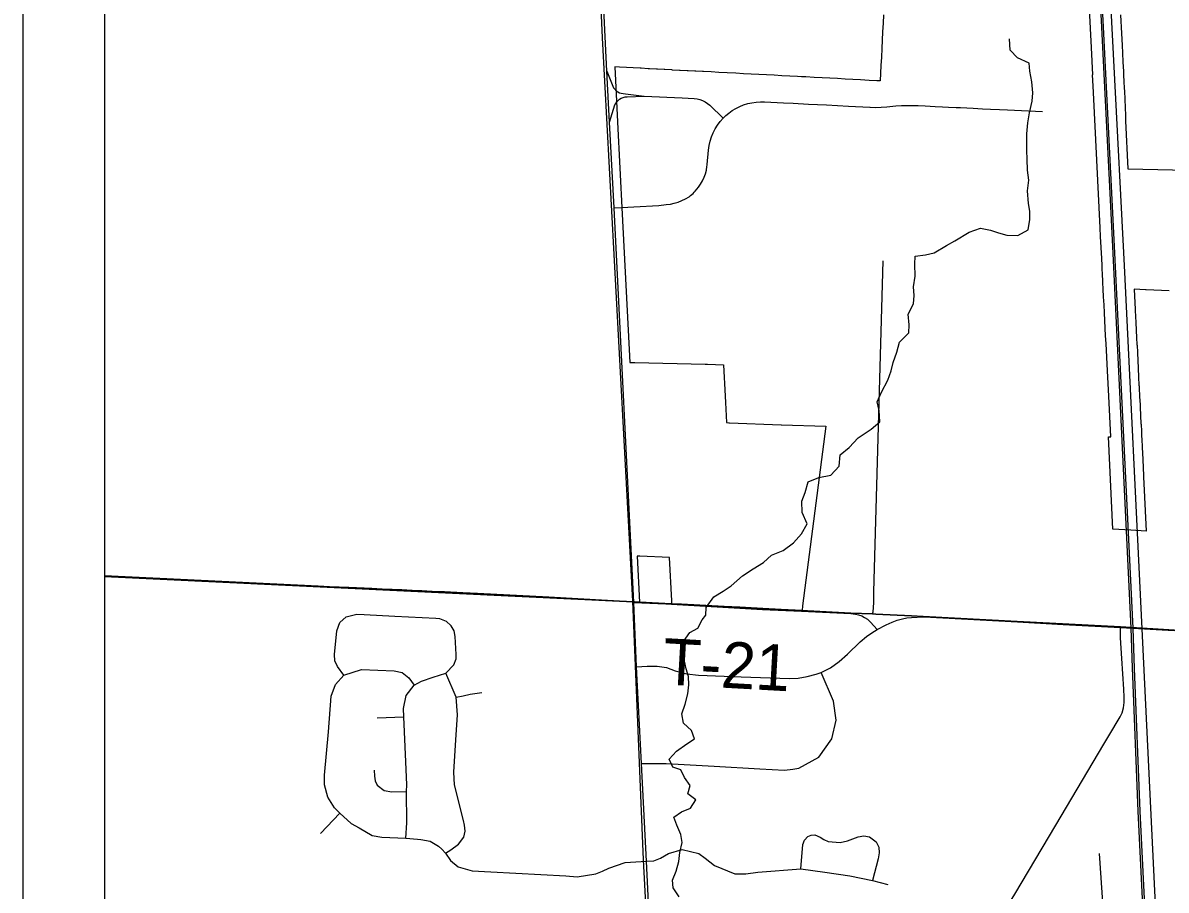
# Model space of a CAD drawing. Extents: x 0 to 34, y 0 to 22.
# Drawn here: x 22.011 to 23.415, y 8.323 to 9.388 of the extents above; entities that cross this region are included whole.
import ezdxf

# ---------------------------------------------------------------- set-up
doc = ezdxf.new("R2010")
doc.units = 0
for name, color, linetype in [('GM_X_City_Street', 7, 'Continuous'), ('GM_X_Corporation', 7, 'Continuous'), ('GM_X_County_Road', 7, 'Continuous'), ('GM_X_Minor_River', 7, 'Continuous'), ('GM_X_Rail_Line', 7, 'Continuous'), ('GM_X_Township_Road', 7, 'Continuous'), ('GM_X_Township_Road_Text', 7, 'Continuous'), ('GM_X_US_Route', 7, 'Continuous'), ('SH_Data', 7, 'Continuous')]:
    doc.layers.add(name, color=color, linetype=linetype)

msp = doc.modelspace()

# ---------------------------------------------------------------- linework, layer by layer
at = {"layer": 'GM_X_City_Street'}
for p, q in [((22.4461, 8.5349), (22.4786, 8.5364)), ((22.3764, 8.3929), (22.4001, 8.418))]:
    msp.add_line(p, q, dxfattribs=at)
for points in [[(22.728, 9.3292), (22.7362, 9.3086), (22.7376, 9.3067), (22.7393, 9.305), (22.7413, 9.3037), (22.7434, 9.3026), (22.7456, 9.3019), (22.748, 9.3015), (22.7509, 9.301), (22.7737, 9.2983)], [(22.7313, 9.2663), (22.7378, 9.2875), (22.7388, 9.2895), (22.7401, 9.2913), (22.7417, 9.2931), (22.7436, 9.2947), (22.7457, 9.2959), (22.748, 9.2968), (22.7504, 9.2974), (22.7529, 9.2976), (22.7737, 9.2983)], [(22.737, 9.1611), (22.7465, 9.1615), (22.761, 9.1625), (22.7916, 9.1642), (22.8009, 9.1652), (22.8059, 9.1658), (22.8107, 9.1669), (22.8155, 9.1683), (22.8201, 9.1701), (22.8246, 9.1723), (22.8289, 9.1748), (22.8308, 9.1765), (22.8322, 9.1776), (22.8339, 9.179), (22.8351, 9.1803), (22.8364, 9.1817), (22.8384, 9.1841), (22.8405, 9.1865), (22.8431, 9.1904), (22.8454, 9.1944), (22.8474, 9.1987), (22.849, 9.203), (22.8502, 9.2075), (22.8504, 9.2084), (22.8509, 9.2113), (22.8513, 9.2143), (22.8529, 9.2321), (22.8537, 9.2376), (22.8549, 9.2429), (22.8565, 9.2482), (22.8585, 9.2532), (22.861, 9.2581), (22.8639, 9.2628), (22.8671, 9.2673), (22.8707, 9.2714), (22.874, 9.2747), (22.8776, 9.2776), (22.8819, 9.2807), (22.8864, 9.2833), (22.8911, 9.2856), (22.8959, 9.2876), (22.9009, 9.2891), (22.906, 9.2903), (22.9112, 9.291), (22.9164, 9.2914), (22.9216, 9.2913), (22.9448, 9.2901), (22.9565, 9.2896), (22.9757, 9.2886), (22.9977, 9.2877), (23.0248, 9.2862), (23.0506, 9.2849), (23.0513, 9.2848), (23.058, 9.2845), (23.0648, 9.2846), (23.0715, 9.2852), (23.0827, 9.2863), (23.0897, 9.2868), (23.0968, 9.287), (23.1038, 9.2868), (23.11, 9.2867), (23.1189, 9.2865), (23.1309, 9.2858), (23.1399, 9.2853), (23.1475, 9.2849), (23.1569, 9.2844), (23.162, 9.2843), (23.1777, 9.2835), (23.1893, 9.2829), (23.199, 9.2825), (23.21, 9.2818), (23.2197, 9.2815), (23.2628, 9.2794)], [(22.7737, 9.2983), (22.8203, 9.2964), (22.8353, 9.2956), (22.8388, 9.2951), (22.8422, 9.2943), (22.8455, 9.2931), (22.8486, 9.2915), (22.8515, 9.2895), (22.8542, 9.2872), (22.8707, 9.2714)], [(22.4049, 8.5874), (22.3975, 8.5981), (22.3942, 8.6051), (22.3937, 8.6128), (22.3965, 8.642), (22.4002, 8.6519), (22.4078, 8.6591), (22.4211, 8.6621), (22.4301, 8.6617), (22.4678, 8.6598), (22.518, 8.6574), (22.5227, 8.6569), (22.5307, 8.6538)], [(22.4813, 8.3874), (22.4823, 8.4062), (22.4822, 8.4446), (22.4823, 8.4526), (22.481, 8.4809), (22.4786, 8.5364), (22.4783, 8.5466), (22.4814, 8.5625), (22.4914, 8.5752), (22.5006, 8.5799), (22.5149, 8.5849), (22.5302, 8.5899), (22.5402, 8.6), (22.5429, 8.6076), (22.5431, 8.6128), (22.5418, 8.635), (22.5404, 8.6418), (22.537, 8.6479), (22.5307, 8.6538)], [(22.7643, 8.5978), (22.7776, 8.5985), (22.7899, 8.5985), (22.8013, 8.5968), (22.812, 8.5928), (22.8261, 8.589), (22.8406, 8.5873), (22.8927, 8.5853), (22.9521, 8.5834), (22.963, 8.5838), (22.9738, 8.5857), (22.9849, 8.5886), (22.9912, 8.5908), (23.0024, 8.5965), (23.0131, 8.6041), (23.0233, 8.6133), (23.039, 8.6284), (23.0465, 8.635), (23.0531, 8.6395), (23.0599, 8.6435)], [(22.4001, 8.418), (22.3936, 8.4247), (22.3853, 8.4377), (22.3814, 8.4526), (22.3815, 8.4645), (22.3861, 8.5179), (22.3896, 8.5617), (22.3947, 8.5761), (22.4049, 8.5874), (22.4269, 8.5945), (22.4669, 8.5928), (22.4768, 8.5905), (22.4847, 8.5842), (22.4914, 8.5752)], [(22.53, 8.3687), (22.5366, 8.3731), (22.546, 8.38), (22.5523, 8.3885), (22.554, 8.3957), (22.5534, 8.4031), (22.552, 8.4088), (22.5408, 8.4526), (22.54, 8.4685), (22.5424, 8.5079), (22.5446, 8.5387), (22.5431, 8.5604), (22.5302, 8.5899)], [(22.7703, 8.479), (22.8009, 8.479), (22.8598, 8.4755), (22.9156, 8.4724), (22.9459, 8.4709), (22.9564, 8.472), (22.9637, 8.4732), (22.9881, 8.4866), (23.0043, 8.5093), (23.0096, 8.5322), (23.0063, 8.5555), (22.9912, 8.5908)], [(22.5431, 8.5604), (22.5516, 8.562), (22.5603, 8.5641), (22.5745, 8.566)], [(22.4422, 8.4707), (22.4426, 8.4635), (22.4435, 8.4577), (22.4461, 8.4525), (22.4545, 8.4457), (22.4642, 8.4442), (22.4822, 8.4446)], [(22.4001, 8.418), (22.4142, 8.4054), (22.4239, 8.3998)], [(22.4239, 8.3998), (22.4397, 8.3907), (22.4519, 8.3886), (22.4813, 8.3874), (22.4957, 8.386), (22.4995, 8.3858), (22.511, 8.3834), (22.5212, 8.3774), (22.5254, 8.3737), (22.53, 8.3687), (22.5359, 8.3597), (22.5456, 8.3521), (22.5626, 8.3473), (22.5857, 8.3458), (22.6777, 8.3409), (22.6915, 8.3399), (22.7145, 8.3433), (22.7227, 8.3467), (22.7302, 8.3504), (22.7505, 8.3573), (22.7637, 8.3584), (22.7765, 8.3589)], [(22.966, 8.3495), (22.9684, 8.3793), (22.9705, 8.385), (22.9748, 8.3893), (22.9789, 8.391), (22.9834, 8.3914), (22.9897, 8.3887), (22.9944, 8.3858), (22.9998, 8.3832), (23.0143, 8.3818), (23.0235, 8.3842), (23.0364, 8.389), (23.0434, 8.3902), (23.0505, 8.3891), (23.0587, 8.3826), (23.0617, 8.3763), (23.0622, 8.3693), (23.0609, 8.3619), (23.0542, 8.3352)], [(22.7765, 8.3589), (22.7855, 8.3595), (22.7938, 8.3628), (22.8037, 8.3684), (22.8206, 8.3734), (22.8409, 8.3686), (22.8488, 8.3629), (22.8601, 8.3539), (22.8852, 8.3435), (22.8986, 8.3434), (22.9132, 8.3454), (22.966, 8.3495), (22.9956, 8.3457), (23.0262, 8.3411), (23.0542, 8.3352), (23.073, 8.3303)]]:
    msp.add_lwpolyline(points, dxfattribs=at)
at = {"layer": 'GM_X_Corporation'}
for points in [[(28.9111, 10.1841), (22.1111, 10.1841), (22.1111, 8.7084), (22.7607, 8.6773), (22.8071, 8.675), (22.9188, 8.6685), (22.9669, 8.6666), (23.0273, 8.6636), (23.054, 8.6627), (23.0581, 8.6625), (23.1019, 8.6602), (23.1162, 8.6596), (23.2317, 8.6532), (23.3585, 8.6466), (23.4244, 8.6428), (23.5205, 8.6353), (24.095, 8.6001), (24.992, 8.5491), (25.0373, 8.5442), (25.1633, 8.5399)], [(26.5463, 10.1841), (22.1111, 10.1841), (22.1111, 8.7084), (22.7607, 8.6773), (22.8071, 8.675), (22.9188, 8.6685), (22.9669, 8.6666), (23.0273, 8.6636), (23.054, 8.6627), (23.0581, 8.6625), (23.1019, 8.6602), (23.1162, 8.6596), (23.2317, 8.6532), (23.3585, 8.6466), (23.4244, 8.6428), (23.5205, 8.6353), (24.095, 8.6001), (24.992, 8.5491), (25.0373, 8.5442), (25.1633, 8.5399)], [(23.4181, 9.0592), (23.3901, 9.0606), (23.3894, 9.0607), (23.3753, 9.0614), (23.3765, 9.0365), (23.3766, 9.0353), (23.3773, 9.0203), (23.3778, 9.0109), (23.3783, 9.0014), (23.3787, 8.9934), (23.3788, 8.9923), (23.3792, 8.9838), (23.3792, 8.9827), (23.3797, 8.9743), (23.3797, 8.9732), (23.3802, 8.9648), (23.3802, 8.9637), (23.3807, 8.9543), (23.3807, 8.9533), (23.3812, 8.9435), (23.3813, 8.9423), (23.382, 8.9275), (23.3821, 8.9265), (23.3826, 8.9171), (23.3826, 8.9161), (23.3831, 8.9067), (23.3831, 8.9057), (23.3836, 8.8963), (23.3837, 8.8953), (23.3841, 8.8869), (23.3842, 8.8858), (23.3844, 8.8805), (23.3846, 8.8774), (23.3846, 8.8764), (23.385, 8.868), (23.3851, 8.8669), (23.3858, 8.8526), (23.3858, 8.8517), (23.3867, 8.8327), (23.3868, 8.831), (23.3901, 8.7642), (23.3712, 8.7654), (23.3493, 8.7666), (23.3436, 8.88), (23.3467, 8.88), (23.3441, 8.93), (23.3425, 8.9609), (23.3408, 8.9946), (23.3403, 9.0041), (23.3398, 9.0136), (23.3393, 9.0227), (23.3388, 9.0323), (23.3383, 9.042), (23.3378, 9.0521), (23.3373, 9.0615), (23.3369, 9.0697), (23.3369, 9.0709), (23.3364, 9.0803), (23.3361, 9.0859), (23.3359, 9.0897), (23.3359, 9.0905), (23.3354, 9.0991), (23.334, 9.1262), (23.3335, 9.1367), (23.3254, 9.3029), (23.325, 9.3104), (23.3243, 9.3243), (23.3246, 9.3243), (23.3228, 9.3582), (23.3184, 9.445)], [(23.0675, 9.3983), (23.067, 9.3879), (23.0665, 9.3775), (23.066, 9.3671), (23.0655, 9.3567), (23.065, 9.3463), (23.0645, 9.3359), (23.064, 9.3264), (23.0636, 9.317), (23.0592, 9.3172), (23.0498, 9.3177), (23.0394, 9.3183), (23.0299, 9.3188), (23.0205, 9.3193), (23.011, 9.3198), (23.0015, 9.3203), (22.9921, 9.3208), (22.9826, 9.3213), (22.9722, 9.3219), (22.9671, 9.3221), (22.9618, 9.3224), (22.9524, 9.3229), (22.9429, 9.3234), (22.9335, 9.3239), (22.924, 9.3244), (22.9146, 9.3249), (22.9051, 9.3254), (22.8956, 9.3259), (22.8862, 9.3264), (22.8758, 9.3269), (22.8654, 9.3275), (22.8559, 9.328), (22.8465, 9.3285), (22.8455, 9.3285), (22.837, 9.329), (22.8361, 9.329), (22.8276, 9.3294), (22.8266, 9.3295), (22.8181, 9.3299), (22.8172, 9.33), (22.8086, 9.3304), (22.8077, 9.3305), (22.7992, 9.3309), (22.7982, 9.331), (22.7902, 9.3314), (22.7888, 9.3315), (22.7803, 9.3319), (22.7787, 9.332), (22.7699, 9.3325), (22.7689, 9.3325), (22.7434, 9.3339), (22.7377, 9.3342), (22.7411, 9.2668), (22.7411, 9.2664), (22.7469, 9.1534), (22.756, 8.9715), (22.7622, 8.9713), (22.8488, 8.9692), (22.8508, 8.9691), (22.8517, 8.9691), (22.8711, 8.9686), (22.8731, 8.9301), (22.8735, 8.9222), (22.8748, 8.8975), (22.8777, 8.8974), (22.8787, 8.8974), (22.9419, 8.8948), (22.9424, 8.8948), (22.9967, 8.8931), (22.9683, 8.6726), (22.9676, 8.6669), (22.942, 8.6682), (22.9196, 8.6694), (22.8913, 8.6708), (22.8721, 8.6718), (22.8194, 8.6744), (22.8078, 8.675), (22.8076, 8.6788), (22.8049, 8.7317), (22.7683, 8.7335), (22.7653, 8.7336), (22.768, 8.6771), (22.7619, 8.6774), (22.7508, 8.678), (22.7505, 8.6778), (22.6782, 8.6819), (22.6569, 8.6831), (22.5693, 8.6877), (22.5511, 8.6885), (22.5287, 8.6896), (22.5134, 8.6903), (22.5009, 8.6909), (22.4889, 8.6914), (22.4764, 8.692), (22.4644, 8.6926), (22.452, 8.6931), (22.4394, 8.6937), (22.4112, 8.695), (22.3875, 8.696), (22.3734, 8.6967), (22.2047, 8.7049), (22.1111, 8.7094), (22.1111, 8.0208)], [(23.3586, 9.3983), (23.3598, 9.3752), (23.3605, 9.361), (23.361, 9.3513), (23.3615, 9.3405), (23.3622, 9.3284), (23.3624, 9.3237), (23.3628, 9.3167), (23.3632, 9.3076), (23.3633, 9.3049), (23.3639, 9.2943), (23.3645, 9.2747), (23.3648, 9.2682), (23.3677, 9.2092), (23.5325, 9.2053)], [(25.1633, 8.5399), (25.0373, 8.5442), (24.992, 8.5491), (24.095, 8.6001), (23.5205, 8.6353), (23.4244, 8.6428), (23.3585, 8.6466), (23.2317, 8.6532), (23.1162, 8.6596), (23.1019, 8.6602), (23.0581, 8.6625), (23.054, 8.6627), (23.0273, 8.6636), (22.9669, 8.6666), (22.9188, 8.6685), (22.8071, 8.675), (22.7607, 8.6773), (22.1111, 8.7084), (22.1111, 3.3841)], [(25.1633, 8.5399), (25.0373, 8.5442), (24.992, 8.5491), (24.095, 8.6001), (23.5205, 8.6353), (23.4244, 8.6428), (23.3585, 8.6466), (23.2317, 8.6532), (23.1162, 8.6596), (23.1019, 8.6602), (23.0581, 8.6625), (23.054, 8.6627), (23.0273, 8.6636), (22.9669, 8.6666), (22.9188, 8.6685), (22.8071, 8.675), (22.7607, 8.6773), (22.1111, 8.7084), (22.1111, 3.5747)]]:
    msp.add_lwpolyline(points, dxfattribs=at)
at = {"layer": 'GM_X_County_Road'}
for p, q in [((22.7609, 8.6768), (22.8004, 8.6748)), ((23.2882, 8.6497), (23.3587, 8.646)), ((23.3587, 8.646), (23.4246, 8.6422))]:
    msp.add_line(p, q, dxfattribs=at)
for points in [[(22.8004, 8.6748), (22.8073, 8.6744), (22.919, 8.668)], [(22.919, 8.668), (22.9671, 8.666), (23.0275, 8.6631)], [(23.0275, 8.6631), (23.0331, 8.6625), (23.0369, 8.6616), (23.0408, 8.6602), (23.0443, 8.6584), (23.0478, 8.656), (23.0516, 8.6526), (23.0599, 8.6435)], [(23.0599, 8.6435), (23.0707, 8.6493), (23.0782, 8.6526), (23.0842, 8.6548), (23.0907, 8.6567), (23.0961, 8.6579), (23.102, 8.6584), (23.1164, 8.6591)], [(23.1164, 8.6591), (23.1174, 8.659), (23.2319, 8.6527), (23.2882, 8.6497)], [(23.3381, 8.5025), (23.3442, 8.5129), (23.3581, 8.5361), (23.3606, 8.5413), (23.3623, 8.5474), (23.363, 8.5538), (23.363, 8.5604), (23.3626, 8.5703), (23.3602, 8.6077), (23.3585, 8.6332), (23.3585, 8.6411), (23.3587, 8.646)], [(23.0226, 7.9875), (23.0332, 8.0042), (23.0475, 8.0269), (23.0562, 8.041), (23.0848, 8.0882), (23.1209, 8.1451), (23.1938, 8.2617), (23.229, 8.3184), (23.2793, 8.4034), (23.3381, 8.5025)]]:
    msp.add_lwpolyline(points, dxfattribs=at)
at = {"layer": 'GM_X_Minor_River'}
for points in [[(22.8495, 8.6612), (22.8499, 8.6703), (22.8594, 8.6835), (22.8707, 8.6907), (22.8806, 8.6972), (22.8946, 8.7093), (22.9074, 8.718), (22.9203, 8.7256), (22.9301, 8.7347), (22.9445, 8.7404), (22.957, 8.7499), (22.9668, 8.7609), (22.974, 8.7734), (22.9676, 8.7871), (22.9672, 8.8011), (22.9714, 8.8117), (22.9751, 8.8246), (22.988, 8.83), (23.0028, 8.833), (23.013, 8.844), (23.0145, 8.858), (23.0254, 8.8668), (23.0364, 8.8789), (23.0523, 8.8895), (23.0629, 8.8986), (23.0621, 8.9123), (23.0599, 8.9229), (23.0651, 8.935), (23.0727, 8.9498), (23.0769, 8.9612), (23.0795, 8.9711), (23.084, 8.984), (23.0874, 8.9961), (23.0988, 9.0079), (23.0992, 9.0174), (23.098, 9.0307), (23.1045, 9.0432), (23.1052, 9.0534), (23.1044, 9.0644), (23.1063, 9.0773), (23.1059, 9.0921), (23.1063, 9.102), (23.1192, 9.1035), (23.1298, 9.1058), (23.1449, 9.1149), (23.1551, 9.1206), (23.1729, 9.1312), (23.1865, 9.1361), (23.199, 9.1338), (23.2089, 9.1304), (23.2191, 9.1278), (23.2323, 9.1274), (23.2452, 9.1342), (23.2471, 9.1467), (23.2471, 9.157), (23.2456, 9.1664), (23.2444, 9.182), (23.2459, 9.1953), (23.2444, 9.2074), (23.244, 9.2211), (23.2436, 9.2317), (23.2436, 9.2522), (23.2448, 9.2655), (23.2466, 9.278), (23.25, 9.292), (23.2508, 9.3023), (23.2497, 9.316), (23.2474, 9.3289), (23.2462, 9.3387), (23.2319, 9.3452), (23.2231, 9.3547), (23.2224, 9.3687)], [(22.8168, 8.3152), (22.8093, 8.3263), (22.8086, 8.3358), (22.8132, 8.3467), (22.8163, 8.3585), (22.8175, 8.3695), (22.8206, 8.382), (22.8187, 8.3919), (22.8139, 8.4033), (22.8102, 8.4132), (22.8196, 8.4196), (22.8306, 8.4241), (22.8371, 8.4343), (22.8273, 8.4419), (22.8304, 8.4518), (22.8233, 8.4617), (22.8188, 8.4712), (22.809, 8.4743), (22.8045, 8.4842), (22.8136, 8.494), (22.8262, 8.503), (22.8357, 8.5091), (22.8319, 8.5193), (22.8221, 8.5285), (22.8199, 8.5399), (22.8242, 8.552), (22.8273, 8.5645), (22.8285, 8.5755), (22.8281, 8.5858), (22.8252, 8.5953), (22.823, 8.6067), (22.823, 8.6162), (22.822, 8.6287), (22.83, 8.6397), (22.8398, 8.6453), (22.8448, 8.6555), (22.8495, 8.6612)]]:
    msp.add_lwpolyline(points, dxfattribs=at)
at = {"layer": 'GM_X_Rail_Line'}
for points in [[(22.7597, 8.6784), (22.7228, 9.3698), (22.6915, 10.0634), (22.676, 10.1841)], [(23.3717, 8.6452), (23.3489, 9.1139), (23.326, 9.5706), (23.3003, 10.0747), (23.2952, 10.1841)], [(23.3741, 8.6453), (23.3513, 9.114), (23.3284, 9.5707), (23.3026, 10.0748), (23.2976, 10.1841)], [(23.385, 8.6444), (23.3634, 9.0905), (23.3382, 9.5786), (23.3148, 10.0727), (23.3094, 10.1841)], [(22.5878, 3.3841), (22.594, 3.5037), (22.6299, 4.2973), (22.6895, 5.4024), (22.7439, 6.4545), (22.7966, 7.4283), (22.8069, 7.7148), (22.7993, 7.8688), (22.773, 8.3605), (22.7597, 8.6784)], [(23.4053, 7.9155), (23.3803, 8.4203), (23.3733, 8.5965), (23.3717, 8.6452)], [(23.4077, 7.9156), (23.3827, 8.4205), (23.3758, 8.5955), (23.3741, 8.6453)], [(23.4127, 8.0775), (23.385, 8.6444)]]:
    msp.add_lwpolyline(points, dxfattribs=at)
at = {"layer": 'GM_X_Township_Road'}
for p, q in [((22.7609, 8.6768), (22.8004, 8.6748)), ((23.2882, 8.6497), (23.3587, 8.646)), ((23.3587, 8.646), (23.4246, 8.6422))]:
    msp.add_line(p, q, dxfattribs=at)
for points in [[(23.0542, 8.6622), (23.055, 8.6653), (23.0557, 8.6764), (23.0559, 8.6898), (23.0671, 9.096)], [(22.8004, 8.6748), (22.8073, 8.6744), (22.919, 8.668)], [(22.919, 8.668), (22.9671, 8.666), (23.0275, 8.6631)], [(23.1164, 8.6591), (23.1174, 8.659), (23.2319, 8.6527), (23.2882, 8.6497)], [(23.3448, 8.2078), (23.3414, 8.2429), (23.3328, 8.3683)]]:
    msp.add_lwpolyline(points, dxfattribs=at)
at = {"layer": 'GM_X_US_Route'}
msp.add_line((22.7643, 8.5978), (22.7609, 8.6768), dxfattribs=at)
for points in [[(22.7609, 8.6768), (22.737, 9.1611), (22.7313, 9.2663), (22.728, 9.3292), (22.7059, 9.7875), (22.6973, 9.9675)], [(22.7949, 8.0297), (22.7921, 8.0696), (22.7845, 8.1978), (22.7765, 8.3589), (22.7703, 8.479), (22.7643, 8.5978)]]:
    msp.add_lwpolyline(points, dxfattribs=at)
at = {"layer": 'SH_Data'}
for p, q in [((22.0111, 10.2841), (22.0111, 3.2841)), ((22.1111, 10.1841), (22.1111, 3.3841))]:
    msp.add_line(p, q, dxfattribs=at)

# ---------------------------------------------------------------- texts
at = {"layer": 'GM_X_Township_Road_Text'}
msp.add_text('T-21', height=0.05682, rotation=356.8199, dxfattribs=at).set_placement((22.7955, 8.5762))

doc.saveas('drawing.dxf')
